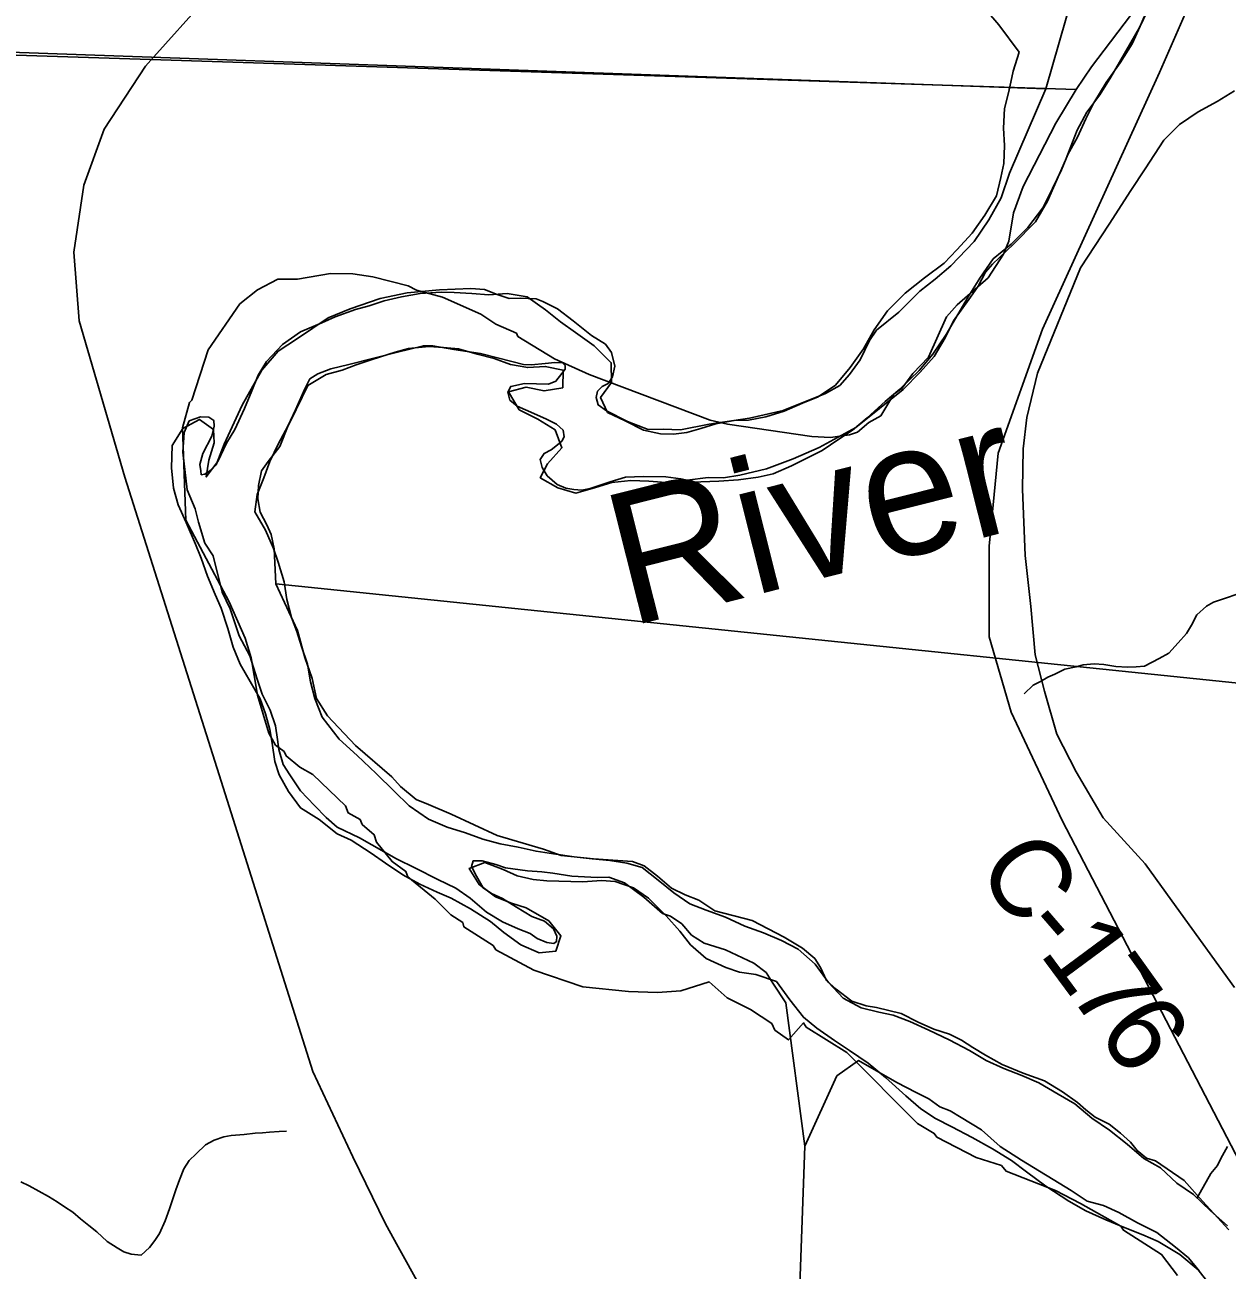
# Model space of a CAD drawing. Extents: x -7.5 to 26.5, y 3.5 to 25.5.
# Drawn here: x 0.131 to 0.992, y 20.216 to 21.108 of the extents above; entities that cross this region are included whole.
import ezdxf

# ---------------------------------------------------------------- set-up
doc = ezdxf.new("R2010")
doc.units = 0
for name, color, linetype in [('GM_X_Corporation', 7, 'Continuous'), ('GM_X_County_Road', 7, 'Continuous'), ('GM_X_County_Road_Text', 7, 'Continuous'), ('GM_X_Major_River', 7, 'Continuous'), ('GM_X_Major_River_Text', 7, 'Continuous'), ('GM_X_Minor_River', 7, 'Continuous'), ('GM_X_Rail_Line', 7, 'Continuous'), ('GM_X_State_Route', 7, 'Continuous')]:
    doc.layers.add(name, color=color, linetype=linetype)

msp = doc.modelspace()

# ---------------------------------------------------------------- linework, layer by layer
at = {"layer": 'GM_X_Corporation'}
msp.add_lwpolyline([(-0.1108, 22.04288), (1.05083, 22.01588), (1.04413, 21.59855), (1.04397, 21.59211), (1.04105, 21.37738), (0.96088, 21.274), (0.94995, 21.26063), (0.9418, 21.25249), (0.98454, 21.25146), (0.95603, 21.20237), (0.92538, 21.1728), (0.90598, 21.15396), (0.88149, 21.12841), (0.86245, 21.06182), (-0.27046, 21.10184)], close=True, dxfattribs=at)
for points in [[(1.30558, 20.60477), (0.31096, 20.70735), (0.30967, 20.73239), (0.30764, 20.74266), (0.3044, 20.74956), (0.2997, 20.75877), (0.29804, 20.76828), (0.29865, 20.77773), (0.3008, 20.78829), (0.30551, 20.795), (0.31372, 20.80578), (0.31977, 20.82079), (0.32497, 20.83203), (0.33178, 20.84702), (0.33536, 20.85413), (0.34113, 20.85778), (0.35031, 20.86134), (0.36326, 20.86444), (0.39719, 20.87308), (0.41663, 20.87792), (0.42344, 20.87775), (0.43853, 20.87511), (0.45741, 20.87238), (0.47059, 20.86903), (0.48828, 20.86444), (0.49396, 20.8643), (0.50383, 20.86519), (0.51067, 20.86578), (0.51635, 20.86564), (0.5182, 20.8637), (0.51813, 20.86106), (0.51578, 20.85808), (0.51148, 20.85251), (0.50612, 20.85036), (0.48909, 20.85077), (0.47919, 20.84874), (0.47719, 20.84462), (0.47857, 20.83891), (0.48377, 20.83461), (0.49577, 20.8294), (0.50476, 20.82539), (0.51187, 20.82181), (0.51669, 20.81752), (0.51733, 20.81258), (0.51574, 20.80959), (0.51265, 20.80701), (0.50801, 20.80334), (0.50303, 20.80081), (0.50027, 20.79633), (0.50164, 20.79061), (0.50529, 20.78484), (0.51234, 20.77861), (0.51871, 20.7758), (0.52437, 20.7749), (0.53004, 20.77439), (0.53613, 20.77576), (0.55027, 20.78034), (0.56133, 20.78386), (0.57423, 20.7843), (0.59013, 20.78392), (0.60108, 20.78252), (0.60561, 20.78164), (0.62043, 20.78356), (0.63141, 20.7833), (0.6432, 20.78528), (0.66225, 20.78974), (0.68136, 20.79686), (0.70013, 20.80512), (0.72623, 20.81926), (0.74323, 20.83286), (0.76023, 20.84646), (0.77228, 20.85905), (0.7824, 20.87017), (0.79031, 20.88362), (0.79628, 20.8956), (0.80844, 20.91272), (0.81394, 20.92055), (0.8191, 20.93066), (0.82417, 20.93621), (0.83929, 20.95062), (0.85483, 20.96654), (0.86353, 20.98147), (0.87636, 21.01071), (0.88484, 21.0321), (0.89159, 21.0452), (0.90099, 21.05747), (0.90887, 21.07016), (0.92943, 21.10565), (0.94062, 21.12925)], [(0.07287, 21.08754), (0.22111, 21.08276), (0.88417, 21.06136), (0.89504, 21.07761), (0.92744, 21.12026)], [(0.92744, 21.12026), (0.89504, 21.07761), (0.88417, 21.06136), (0.86951, 21.03711), (0.84617, 20.99199), (0.83931, 20.97313), (0.83585, 20.95268), (0.83197, 20.94334), (0.821, 20.92647), (0.79896, 20.90717), (0.79118, 20.8986), (0.77843, 20.8696), (0.76717, 20.85806), (0.75936, 20.84758), (0.75358, 20.84314), (0.74414, 20.82776), (0.73569, 20.82299), (0.72757, 20.81595), (0.72184, 20.81417), (0.70814, 20.81218), (0.69487, 20.81284), (0.63435, 20.82173), (0.62189, 20.82465), (0.53531, 20.85728), (0.5105, 20.86845), (0.48428, 20.88459), (0.48319, 20.8869), (0.46853, 20.89329), (0.45767, 20.90036), (0.43024, 20.91273), (0.41175, 20.91768), (0.40575, 20.92085), (0.38046, 20.92709), (0.36608, 20.92929), (0.35015, 20.92963), (0.32654, 20.92558), (0.3125, 20.92549), (0.29791, 20.91782), (0.28518, 20.90783), (0.26247, 20.87487), (0.2507, 20.83901), (0.24907, 20.83734), (0.24413, 20.8192), (0.24651, 20.75301), (0.27753, 20.69458), (0.28911, 20.66849), (0.29337, 20.65434), (0.29773, 20.62763), (0.30588, 20.60047), (0.31063, 20.59201), (0.31698, 20.58731), (0.31844, 20.58424), (0.32813, 20.57605), (0.33751, 20.57092), (0.36093, 20.54837), (0.36272, 20.5434), (0.37135, 20.53865), (0.37279, 20.53519), (0.38136, 20.52779), (0.38315, 20.52244), (0.39424, 20.50852), (0.40396, 20.50147), (0.40539, 20.49764), (0.42516, 20.48163), (0.43631, 20.47037), (0.44491, 20.46487), (0.44561, 20.46182), (0.46657, 20.44844), (0.46841, 20.44537), (0.49579, 20.43072), (0.53083, 20.41895), (0.56339, 20.4156), (0.58425, 20.41478), (0.60097, 20.41594), (0.62122, 20.42235), (0.63426, 20.41106), (0.65078, 20.40272), (0.66612, 20.39251), (0.6683, 20.3879), (0.67801, 20.38086), (0.68889, 20.39309), (0.69072, 20.39), (0.71993, 20.3719), (0.77045, 20.32104), (0.78245, 20.31394), (0.78429, 20.31125), (0.81244, 20.29659), (0.83053, 20.29088), (0.83386, 20.28701), (0.86923, 20.27296), (0.88725, 20.26383), (0.91613, 20.24764), (0.91796, 20.24455), (0.94529, 20.22725), (0.95673, 20.21219)], [(-0.27046, 21.10184), (0.86245, 21.06182), (0.83636, 21.00146), (0.83025, 20.9838), (0.82153, 20.9681), (0.81092, 20.95244), (0.79421, 20.93504), (0.78299, 20.92547), (0.77218, 20.91702), (0.75703, 20.90185), (0.74119, 20.88898), (0.73608, 20.88152), (0.7293, 20.86767), (0.72186, 20.85725), (0.71484, 20.84946), (0.70448, 20.84365), (0.67425, 20.83151), (0.65025, 20.82603), (0.62136, 20.8218), (0.6008, 20.81775), (0.58831, 20.81806), (0.5777, 20.81794), (0.56268, 20.82361), (0.54771, 20.83117), (0.54175, 20.83548), (0.54037, 20.84082), (0.54124, 20.84534), (0.54472, 20.84867), (0.54894, 20.85084), (0.5521, 20.85568), (0.55379, 20.86322), (0.55138, 20.87313), (0.54698, 20.87892), (0.5369, 20.88522), (0.5239, 20.89577), (0.51274, 20.90438), (0.50226, 20.90955), (0.49738, 20.91157), (0.48603, 20.91184), (0.47807, 20.91166), (0.46942, 20.91452), (0.46041, 20.91815), (0.45058, 20.91876), (0.4282, 20.91779), (0.40505, 20.91571), (0.38562, 20.91163), (0.36423, 20.90419), (0.34854, 20.89776), (0.32659, 20.88314), (0.31273, 20.874), (0.30103, 20.86027), (0.28679, 20.83523), (0.27399, 20.80751), (0.26832, 20.79249), (0.26405, 20.78843), (0.26021, 20.78587), (0.25755, 20.78555), (0.25723, 20.78821), (0.25658, 20.79277), (0.25867, 20.80068), (0.26503, 20.81303), (0.26672, 20.82019), (0.26644, 20.82436), (0.26309, 20.82671), (0.25703, 20.82686), (0.24901, 20.82402), (0.2454, 20.81578), (0.2443, 20.80179), (0.24743, 20.77481), (0.25316, 20.76103), (0.25558, 20.75151), (0.26014, 20.73662), (0.26598, 20.72738), (0.26738, 20.72242), (0.27049, 20.71023), (0.27255, 20.70146), (0.27832, 20.68958), (0.28467, 20.67011), (0.29228, 20.65591), (0.29755, 20.63911), (0.30108, 20.62841), (0.30687, 20.6169), (0.31076, 20.60582), (0.31204, 20.59594), (0.313, 20.58872), (0.31615, 20.57804), (0.3209, 20.57073), (0.32857, 20.55917), (0.33855, 20.5487), (0.34706, 20.54016), (0.35484, 20.53315), (0.37094, 20.52556), (0.39748, 20.51052), (0.41095, 20.50376), (0.42705, 20.49579), (0.43978, 20.48941), (0.45021, 20.48234), (0.46171, 20.47222), (0.47329, 20.46549), (0.48453, 20.46029), (0.49316, 20.45705), (0.49801, 20.45353), (0.50513, 20.4507), (0.51004, 20.44982), (0.51196, 20.4513), (0.51206, 20.45508), (0.50991, 20.46044), (0.50323, 20.4659), (0.49422, 20.46916), (0.48339, 20.47586), (0.47332, 20.48216), (0.46545, 20.48576), (0.45948, 20.4897), (0.45476, 20.49815), (0.45114, 20.50505), (0.45238, 20.50919), (0.45881, 20.50903), (0.4686, 20.50652), (0.47536, 20.50408), (0.49122, 20.50181), (0.50144, 20.50118), (0.50936, 20.50023), (0.52295, 20.49801), (0.54112, 20.49718), (0.54945, 20.49736), (0.56072, 20.4933), (0.57449, 20.48312), (0.58784, 20.47142), (0.59348, 20.46939), (0.60168, 20.46389), (0.60868, 20.45577), (0.61764, 20.45025), (0.63305, 20.44532), (0.65327, 20.43574), (0.6622, 20.42908), (0.66695, 20.42139), (0.67608, 20.40753), (0.68988, 20.30491), (0.68309, 20.11906)], [(0.95673, 20.21219), (0.94529, 20.22725), (0.91796, 20.24455), (0.91613, 20.24764), (0.88725, 20.26383), (0.86923, 20.27296), (0.83386, 20.28701), (0.83053, 20.29088), (0.81244, 20.29659), (0.78429, 20.31125), (0.78245, 20.31394), (0.77045, 20.32104), (0.71993, 20.3719), (0.69072, 20.39), (0.68889, 20.39309), (0.67801, 20.38086), (0.6683, 20.3879), (0.66612, 20.39251), (0.65078, 20.40272), (0.63426, 20.41106), (0.62122, 20.42235), (0.60097, 20.41594), (0.58425, 20.41478), (0.56339, 20.4156), (0.53083, 20.41895), (0.49579, 20.43072), (0.46841, 20.44537), (0.46657, 20.44844), (0.44561, 20.46182), (0.44491, 20.46487), (0.43631, 20.47037), (0.42516, 20.48163), (0.40539, 20.49764), (0.40396, 20.50147), (0.39424, 20.50852), (0.38315, 20.52244), (0.38136, 20.52779), (0.37279, 20.53519), (0.37135, 20.53865), (0.36272, 20.5434), (0.36093, 20.54837), (0.33751, 20.57092), (0.32813, 20.57605), (0.31844, 20.58424), (0.31698, 20.58731), (0.31063, 20.59201), (0.30588, 20.60047), (0.29773, 20.62763), (0.29337, 20.65434), (0.28911, 20.66849), (0.27753, 20.69458), (0.24651, 20.75301), (0.24413, 20.8192), (0.24907, 20.83734), (0.2507, 20.83901), (0.26247, 20.87487), (0.28518, 20.90783), (0.29791, 20.91782), (0.3125, 20.92549), (0.32654, 20.92558), (0.35015, 20.92963), (0.36608, 20.92929), (0.38046, 20.92709), (0.40575, 20.92085), (0.41175, 20.91768), (0.43024, 20.91273), (0.45767, 20.90036), (0.46853, 20.89329), (0.48319, 20.8869), (0.48428, 20.88459), (0.5105, 20.86845), (0.53531, 20.85728), (0.62189, 20.82465), (0.63435, 20.82173), (0.69487, 20.81284), (0.70814, 20.81218), (0.72184, 20.81417), (0.72757, 20.81595), (0.73569, 20.82299), (0.74414, 20.82776), (0.75358, 20.84314), (0.75936, 20.84758), (0.76717, 20.85806), (0.77843, 20.8696), (0.79118, 20.8986), (0.79896, 20.90717), (0.821, 20.92647), (0.83197, 20.94334), (0.83585, 20.95268), (0.83931, 20.97313), (0.84617, 20.99199), (0.86951, 21.03711), (0.88417, 21.06136), (0.22111, 21.08276), (0.07287, 21.08754)], [(0.99339, 20.24488), (0.97456, 20.26541), (0.96129, 20.28013), (0.94079, 20.29427), (0.9344, 20.29632), (0.92772, 20.30179), (0.92293, 20.30758), (0.91589, 20.31419), (0.90771, 20.32045), (0.89761, 20.32562), (0.89091, 20.33071), (0.88498, 20.33616), (0.87418, 20.34362), (0.86149, 20.35151), (0.84609, 20.35718), (0.83109, 20.36323), (0.81913, 20.36996), (0.81017, 20.37549), (0.80196, 20.38061), (0.79335, 20.38498), (0.78207, 20.38867), (0.77083, 20.39349), (0.75886, 20.39984), (0.74116, 20.40406), (0.73361, 20.40537), (0.72346, 20.40865), (0.7123, 20.41726), (0.70526, 20.42349), (0.70094, 20.43269), (0.69693, 20.43922), (0.68802, 20.44664), (0.67495, 20.45454), (0.65213, 20.46646), (0.62539, 20.47317), (0.61384, 20.48102), (0.60408, 20.48467), (0.59435, 20.48945), (0.58432, 20.49803), (0.57465, 20.50547), (0.5664, 20.50869), (0.53841, 20.51051), (0.51536, 20.51297), (0.50259, 20.51744), (0.46949, 20.52734), (0.43652, 20.54253), (0.42039, 20.54937), (0.41139, 20.553), (0.40025, 20.56236), (0.39398, 20.56933), (0.368, 20.59155), (0.34806, 20.61287), (0.34003, 20.62519), (0.33697, 20.63966), (0.33165, 20.65457), (0.32644, 20.67402), (0.31096, 20.70735), (1.30558, 20.60477)], [(0.68309, 20.11906), (0.68988, 20.30491), (0.71269, 20.35512), (0.72811, 20.36611), (0.75576, 20.35028), (0.76961, 20.34313), (0.77859, 20.33875), (0.78641, 20.33287), (0.79391, 20.33004), (0.80175, 20.3253), (0.81631, 20.31661), (0.82966, 20.30455), (0.84496, 20.2947), (0.88042, 20.27301), (0.89198, 20.26553), (0.90365, 20.26221), (0.91452, 20.2574), (0.92797, 20.24988), (0.94182, 20.2431), (0.9552, 20.23254), (0.96449, 20.22474), (0.97222, 20.21546)]]:
    msp.add_lwpolyline(points, dxfattribs=at)
at = {"layer": 'GM_X_County_Road'}
msp.add_lwpolyline([(0.99735, 20.41835), (0.95565, 20.47627), (0.93353, 20.50699), (0.90351, 20.53985), (0.88412, 20.57275), (0.87021, 20.59979), (0.86136, 20.63045), (0.85463, 20.65649), (0.85159, 20.69115), (0.84748, 20.72775), (0.84563, 20.77528), (0.84619, 20.80413), (0.84882, 20.82645), (0.85628, 20.85823), (0.88723, 20.93364), (0.90778, 20.96487), (0.92325, 20.98906), (0.93338, 21.00454), (0.94689, 21.02508), (0.958, 21.03633), (0.97136, 21.04533), (0.98515, 21.05265), (0.99753, 21.06039)], dxfattribs=at)
at = {"layer": 'GM_X_Major_River'}
for points in [[(0.77551, 21.24976), (0.77093, 21.24194), (0.77703, 21.23035), (0.78806, 21.21899), (0.79565, 21.20659), (0.80168, 21.19273), (0.80659, 21.17965), (0.8081, 21.16745), (0.80895, 21.15792), (0.81154, 21.14378), (0.81422, 21.1323), (0.81839, 21.11963), (0.82864, 21.10753), (0.84323, 21.08808)], [(0.4064, 20.54837), (0.39572, 20.55896), (0.38282, 20.57152), (0.36917, 20.58448), (0.35625, 20.59628), (0.3442, 20.61186), (0.33893, 20.62532), (0.33588, 20.6372), (0.33362, 20.64981), (0.32945, 20.66247), (0.32599, 20.67322), (0.32212, 20.68322), (0.31873, 20.69625), (0.31685, 20.70885), (0.31273, 20.72303), (0.30924, 20.73264), (0.30357, 20.74574), (0.296, 20.75889), (0.29753, 20.77138), (0.30246, 20.78339), (0.30662, 20.79504), (0.31271, 20.80739), (0.32157, 20.82384), (0.33376, 20.8493), (0.34692, 20.85725), (0.35841, 20.86031), (0.3684, 20.86418), (0.37991, 20.868), (0.3964, 20.87319), (0.40598, 20.87593), (0.42046, 20.87738), (0.43107, 20.87668), (0.44167, 20.87559), (0.45522, 20.87174), (0.46727, 20.86871), (0.47892, 20.86455), (0.49138, 20.86226), (0.50393, 20.86301), (0.51676, 20.86033), (0.51637, 20.84781), (0.50301, 20.84556), (0.49018, 20.84824), (0.47754, 20.84483), (0.48512, 20.83206), (0.49858, 20.82518), (0.51087, 20.81758), (0.51579, 20.80489), (0.50556, 20.79342), (0.50031, 20.78333), (0.513, 20.77609), (0.52579, 20.77228), (0.5392, 20.77604), (0.55147, 20.77984), (0.56518, 20.78131), (0.57808, 20.78091), (0.59323, 20.77968), (0.60312, 20.78014), (0.61529, 20.78052), (0.62821, 20.78088), (0.64229, 20.78196), (0.6564, 20.7838), (0.6671, 20.78613), (0.68019, 20.7918), (0.69022, 20.79681), (0.70219, 20.8029), (0.7142, 20.81089), (0.7239, 20.81743), (0.73443, 20.82622), (0.74733, 20.83798), (0.75785, 20.84677), (0.77156, 20.86003), (0.78142, 20.87188), (0.79098, 20.88603), (0.79939, 20.9002), (0.80662, 20.9129), (0.81502, 20.92632), (0.82456, 20.94008), (0.83742, 20.9507), (0.84956, 20.96249), (0.86026, 20.9766), (0.86714, 20.99044), (0.87364, 21.00392), (0.87815, 21.0148), (0.88499, 21.02713), (0.8911, 21.04024), (0.89678, 21.05184), (0.90559, 21.06639), (0.91552, 21.08052), (0.92429, 21.09393), (0.93, 21.10667), (0.93575, 21.12055)], [(0.84323, 21.08808), (0.839, 21.07453), (0.83589, 21.05981), (0.83285, 21.04774), (0.83204, 21.03371), (0.83278, 21.02114), (0.83238, 21.00824), (0.83018, 20.99843), (0.82711, 20.98522), (0.8187, 20.97142), (0.80956, 20.95841), (0.79856, 20.94659), (0.78953, 20.93699), (0.77553, 20.9264), (0.76152, 20.91544), (0.74897, 20.90291), (0.73943, 20.88914), (0.7318, 20.8757), (0.72227, 20.86232), (0.71162, 20.84973), (0.69921, 20.84137), (0.68805, 20.83678), (0.67496, 20.8311), (0.66192, 20.82695), (0.64932, 20.82468), (0.63905, 20.82424), (0.62607, 20.82198), (0.61533, 20.81852), (0.60537, 20.81578), (0.59584, 20.81456), (0.58636, 20.81485), (0.57429, 20.81751), (0.5612, 20.824), (0.54848, 20.83009), (0.5435, 20.84088), (0.55143, 20.85166), (0.55111, 20.86573), (0.53895, 20.87788), (0.52558, 20.88742), (0.5148, 20.89498), (0.50406, 20.90367), (0.49105, 20.91281), (0.4767, 20.91516), (0.46338, 20.91443), (0.45126, 20.91519), (0.43875, 20.91596), (0.42926, 20.91625), (0.41442, 20.91519), (0.40106, 20.91295), (0.38843, 20.90992), (0.37769, 20.90645), (0.36811, 20.90371), (0.35352, 20.89846), (0.34389, 20.8942), (0.3285, 20.88784), (0.31569, 20.87874), (0.3043, 20.86655), (0.2983, 20.85686), (0.29377, 20.8456), (0.28844, 20.83285), (0.28151, 20.81786), (0.27552, 20.80817), (0.26941, 20.79506), (0.26109, 20.78392), (0.26298, 20.79602), (0.26679, 20.80844), (0.26633, 20.81795), (0.2563, 20.8251), (0.24432, 20.81864), (0.23672, 20.80633), (0.23623, 20.79039), (0.23767, 20.7759), (0.2411, 20.76402), (0.24678, 20.7513), (0.25351, 20.73589), (0.25738, 20.72589), (0.26191, 20.71283), (0.26758, 20.69974), (0.27184, 20.6901), (0.2767, 20.67551), (0.28045, 20.6621), (0.28539, 20.64978), (0.2998, 20.62502), (0.30365, 20.61426), (0.30672, 20.60314), (0.30831, 20.59321), (0.31018, 20.58024), (0.3133, 20.57064), (0.32014, 20.55865), (0.32851, 20.54699), (0.34192, 20.53859), (0.35489, 20.52831), (0.365, 20.52381), (0.37915, 20.51463), (0.38956, 20.50747), (0.40183, 20.49911), (0.41415, 20.49227), (0.4265, 20.48656), (0.43663, 20.48245), (0.45044, 20.4748), (0.46458, 20.46562)], [(0.99248, 20.24786), (0.98028, 20.2585), (0.96811, 20.27027), (0.95621, 20.27824), (0.9444, 20.28924), (0.93246, 20.29607), (0.92063, 20.30632), (0.90803, 20.31621), (0.89539, 20.32496), (0.88318, 20.33522), (0.87124, 20.34205), (0.85744, 20.35008), (0.84507, 20.3554), (0.83231, 20.36035), (0.81958, 20.36607), (0.80765, 20.37328), (0.79308, 20.38095), (0.77849, 20.38786), (0.76501, 20.39398), (0.753, 20.39853), (0.74281, 20.40075), (0.73, 20.40381), (0.7173, 20.41066), (0.70664, 20.42201), (0.69718, 20.43522), (0.68498, 20.44586), (0.67302, 20.45193), (0.66028, 20.45765), (0.64676, 20.46225), (0.63291, 20.46876), (0.61901, 20.47375), (0.60738, 20.47829), (0.59586, 20.48624), (0.58475, 20.49533), (0.57326, 20.50443), (0.56234, 20.50742), (0.55025, 20.50932), (0.53737, 20.51048), (0.52451, 20.51202), (0.50976, 20.514), (0.49729, 20.51591), (0.48448, 20.51896), (0.47163, 20.52126), (0.45921, 20.52469), (0.44682, 20.52925), (0.43365, 20.53308), (0.42016, 20.53882), (0.4064, 20.54837)], [(0.46458, 20.46562), (0.47421, 20.45772), (0.48647, 20.44898), (0.49958, 20.44326), (0.51139, 20.44441), (0.51515, 20.45531), (0.50637, 20.46622), (0.49033, 20.47546), (0.47981, 20.47883), (0.46817, 20.48337), (0.45667, 20.49209), (0.44944, 20.50371), (0.46059, 20.50792), (0.47372, 20.50296), (0.48384, 20.49846), (0.49514, 20.49583), (0.50498, 20.49477), (0.53078, 20.49397), (0.54411, 20.49507), (0.55396, 20.49439), (0.56711, 20.4898), (0.57789, 20.48224), (0.59041, 20.4697), (0.60032, 20.45875), (0.60799, 20.44901), (0.61908, 20.43917), (0.6333, 20.43264), (0.64307, 20.4293), (0.6548, 20.4278), (0.66945, 20.42278), (0.67891, 20.40957), (0.68878, 20.3971), (0.69841, 20.38921), (0.71104, 20.38046), (0.72183, 20.37328), (0.73522, 20.36413), (0.74743, 20.35387), (0.76221, 20.34087), (0.77293, 20.33142), (0.78335, 20.32463), (0.79494, 20.31857), (0.80951, 20.3109), (0.82407, 20.30285), (0.83785, 20.29445), (0.84862, 20.28651), (0.86235, 20.27621), (0.87872, 20.26544), (0.89104, 20.2586), (0.90527, 20.25208), (0.91914, 20.24633), (0.9319, 20.24137), (0.94276, 20.23648), (0.95842, 20.22725), (0.97137, 20.21621), (0.97904, 20.20648)]]:
    msp.add_lwpolyline(points, dxfattribs=at)
at = {"layer": 'GM_X_Minor_River'}
for points in [[(0.84694, 20.62872), (0.85323, 20.63496), (0.85863, 20.63744), (0.86367, 20.64068), (0.86868, 20.64279), (0.87602, 20.64634), (0.88405, 20.64796), (0.88903, 20.64931), (0.89703, 20.65017), (0.90384, 20.64955), (0.91253, 20.64811), (0.92087, 20.64783), (0.92695, 20.648), (0.93305, 20.64855), (0.94348, 20.65389), (0.95045, 20.65783), (0.95716, 20.66519), (0.96308, 20.67183), (0.96671, 20.67779), (0.97038, 20.68526), (0.97743, 20.69148), (0.98247, 20.69434), (0.99169, 20.69745), (0.9986, 20.69987)], [(0.1283, 20.27924), (0.13428, 20.27637), (0.14806, 20.26867), (0.15439, 20.26503), (0.15958, 20.26144), (0.16552, 20.25743), (0.17105, 20.25268), (0.17696, 20.24791), (0.18288, 20.24353), (0.19023, 20.23643), (0.19729, 20.23201), (0.20212, 20.22918), (0.20738, 20.22747), (0.21457, 20.22685), (0.22046, 20.23234), (0.22442, 20.23715), (0.22764, 20.24236), (0.23175, 20.25134), (0.2347, 20.25997), (0.23723, 20.26711), (0.23935, 20.27349), (0.24187, 20.28063), (0.24518, 20.28849), (0.2488, 20.29445), (0.2539, 20.29921), (0.26059, 20.30582), (0.26677, 20.30903), (0.27369, 20.31145), (0.27904, 20.31241), (0.28818, 20.31323), (0.29618, 20.31409), (0.3015, 20.31429), (0.30646, 20.31488), (0.31331, 20.3154), (0.31863, 20.3156)], [(0.97078, 20.26769), (0.98046, 20.28511), (0.98522, 20.29103), (0.98767, 20.29588), (0.99252, 20.30446)]]:
    msp.add_lwpolyline(points, dxfattribs=at)
at = {"layer": 'GM_X_Rail_Line'}
msp.add_lwpolyline([(1.44307, 19.11009), (1.43574, 19.13421), (1.34268, 19.52848), (1.32404, 19.58202), (1.31306, 19.62574), (1.29522, 19.69677), (1.27132, 19.75532), (1.11302, 20.07849), (0.874, 20.53791), (0.83759, 20.61554), (0.82177, 20.66941), (0.82177, 20.73437), (0.82811, 20.80091), (0.85998, 20.88968), (0.94371, 21.07342), (0.97387, 21.14239), (1.00188, 21.19828), (1.04601, 21.25056), (1.10805, 21.30571), (1.18037, 21.39001), (1.22998, 21.44988), (1.32629, 21.56232), (1.41091, 21.65578), (1.44307, 21.68781)], dxfattribs=at)
at = {"layer": 'GM_X_State_Route'}
msp.add_lwpolyline([(0.5968, 19.87202), (0.58384, 19.89555), (0.48889, 20.07157), (0.43009, 20.17591), (0.39856, 20.23271), (0.38955, 20.24922), (0.36604, 20.29726), (0.33751, 20.35832), (0.27047, 20.57073), (0.20272, 20.78379), (0.17011, 20.8958), (0.16635, 20.94487), (0.17355, 20.99292), (0.18814, 21.03284), (0.21765, 21.0781), (0.22134, 21.08223), (0.26126, 21.12684), (0.35794, 21.22295)], dxfattribs=at)

# ---------------------------------------------------------------- texts
at = {"layer": 'GM_X_County_Road_Text'}
for s, rotation, p in [('C', 303.93824, (0.81182, 20.50454)), ('-', 310.89753, (0.84245, 20.45985)), ('1', 306.51082, (0.85701, 20.44311)), ('7', 305.62298, (0.8777, 20.41517)), ('6', 305.34183, (0.89804, 20.38677))]:
    msp.add_text(s, height=0.05682, rotation=rotation, dxfattribs=at).set_placement(p)
at = {"layer": 'GM_X_Major_River_Text'}
msp.add_text('River', height=0.094698, rotation=14.13624, dxfattribs=at).set_placement((0.56377, 20.67649))

doc.saveas('drawing.dxf')
